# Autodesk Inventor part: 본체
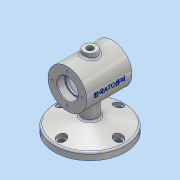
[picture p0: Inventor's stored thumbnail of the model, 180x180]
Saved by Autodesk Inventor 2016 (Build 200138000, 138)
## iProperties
Created: 2018-12
Part Number: 본체
Material: 알루미늄 6061
Document SubType Name: Modeling
Designer: 3sil_cad0123
Density: 2.7 g/cm^3
Appearance: 알루미늄 - 평지
Mass: 685.127 g
Surface Area: 555.63 cm^2
Volume: 253.751 cm^3
Author: 3sil_cad0123
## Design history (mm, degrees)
sketch "스케치1"
  geometry: C1 r 30 at (0, 0); 1 further point
  constraints: 1 centre point, 1 coincident
  dimensions: "d0" = 60 diameter of C1
extrude "돌출1" new body sketch "스케치1" distance "d1" = 70; taper "d2" = 0 deg
node "작업 평면1"
sketch "스케치2"
  geometry: C1 r 25 at (0, 0); 1 further point
  constraints: 1 centre point, 1 coincident
  dimensions: "d3" = 50 diameter of C1
extrude "돌출2" cut sketch "스케치2" stored distance "d4" = 40; taper "d5" = 0 deg
hole "구멍1" diameter "d8" = 28; stored, may be unused: countersink angle "d12" = 90 deg, drill point angle "d14" = 118 deg; dims "d6" = 10, "d7" = 10, "d9" = 6, "d10" = 32, "d11" = 12, "d13" = 8
node "작업 평면2"
sketch "스케치3"
  geometry: C1 r 55 at (0, 35); 1 further point
  constraints: 1 centre point, 1 vertical alignment
  dimensions: "d16" = 110 diameter of C1; "d17" = 35 distance of point (0, 0) C1.centre
extrude "돌출3" join sketch "스케치3" distance "d18" = 11; taper "d19" = 0 deg
sketch "스케치4"
  geometry: C1 r 55 at (0, 0) reference; C2 r 12 at (0, 0); 1 further point
  constraints: 1 centre point, 1 coincident
  dimensions: "d20" = 24 diameter of C2
extrude "돌출4" join sketch "스케치4" stored distance "d21" = 101; taper "d22" = 0 deg
sketch "스케치5"
  geometry: L1 (55, -64)-(55, -75) reference; L2 (55, -75)-(-55, -75) reference; L3 (-55, -75)-(-55, -64) reference; L4 (-55, -64)-(-12, -64) reference; L5 (-12, -64)-(-12, -27.495) reference; L6 (12, -27.495)-(12, -64) reference; L7 (12, -64)-(55, -64) reference; L8 (55, -64)-(-55, -64) reference; L9 (-55, -64)-(4.261, -64); L10 (-55, -64)-(0, -49.263); L11 (-12, -64)-(12, -64) reference; L12 (0, -64)-(0, 0); L13 (-55, -64)-(0, -64); L14 (0, -64)-(55, -64); L15 (0, -49.263)-(55, -64); C1 r 25 at (0, 0) reference; A1 r 30 centre (0, 0) between (12, -27.495) and (-12, -27.495) reference; 1 further point
  constraints: 12 end point, 2 horizontal, 2 point on line, 1 midpoint, 1 vertical
  dimensions: "d96" = 11 distance between parallel lines of L2 L7 (derived); "d97" = 75 deg angle of L1 L15
revolve "회전1" sketch "스케치5" stored, may be unused: angle "d26" = 90 deg
fillet "모깎기1" dims "d27" = 3
node "작업 평면3"
sketch "스케치7"
  geometry: L1 (-30, -35)-(30, -35) reference; C1 r 10 at (0, 0); 1 further point
  constraints: 1 centre point, 1 vertical alignment
  dimensions: "d32" = 20 diameter of C1; "d33" = 35 distance from line of L1 C1.centre
extrude "돌출6" join sketch "스케치7" stored distance "d34" = 40; taper "d35" = 0 deg
fillet "모깎기2" dims "d36" = 3
fillet "모깎기3" dims "d37" = 3
chamfer "모따기1" distance "d38" = 1; stored, may be unused: second distance "d39" = 2, angle "d40" = 45 deg
hole "구멍2" diameter "d43" = 10; stored, may be unused: countersink angle "d47" = 90 deg, drill point angle "d49" = 118 deg; dims "d41" = 10, "d42" = 10, "d44" = 6, "d45" = 32, "d46" = 12, "d48" = 30
fillet "모깎기4" dims "d50" = 3
sketch "스케치8"
  geometry: C1 r 55 at (0, 0) reference; 2 further points
  constraints: 1 horizontal alignment
  dimensions: "d51" = 44 distance of C1.centre point (-44, 0)
hole "구멍3" sketch "스케치8" at (-44, 0) diameter "d52" = 9; stored, may be unused: countersink angle "d56" = 90 deg, drill point angle "d58" = 0 deg; dims "d53" = 6, "d54" = 9, "d55" = 10, "d57" = 10
hole "구멍4" diameter "d61" = 14; stored, may be unused: countersink angle "d65" = 90 deg, drill point angle "d67" = 0 deg; dims "d59" = 10, "d60" = 10, "d62" = 6, "d63" = 9, "d64" = 10, "d66" = 10
sketch "스케치9"
  geometry: C1 r 30 at (0, 0) reference; 1 further point
  constraints: 1 vertical alignment
  dimensions: "d71" = 23 distance of C1.centre point (0, 23)
hole "구멍5" sketch "스케치9" at (0, 23) diameter "d72" = 3.242; stored, may be unused: countersink angle "d76" = 90 deg, drill point angle "d78" = 118 deg; dims "d73" = 8, "d74" = 9, "d75" = 10, "d77" = 10
node "작업 평면6"
sketch "스케치13"
  geometry: L1 (45, 37)-(25, 37) reference; L2 (0, 30)-(70, 30) reference; 2 further points
  constraints: 1 other
  dimensions: "d90" = 35 distance of point (35, 0) point (0, 0); "d92" = 30 distance from line of point (35, 0) L2
feature "엠보싱1" sketch "스케치13" dims "d17" = 35, "d93" = 0.5, "d94" = 0
sketch "스케치14"
  geometry: L1 (-16, -65)-(-13.5, -65) reference; L2 (-13.5, -65)-(-13.5, -75) reference; L3 (-13.5, -75)-(-20, -75) reference; L4 (-20, -75)-(-20, -66.302) reference; L5 (-17.776, -63.404)-(-16, -62.928) reference; L6 (-16, -62.928)-(-16, -65) reference; L7 (83.5, -65)-(86, -65) reference; L8 (86, -65)-(86, -62.928) reference; L9 (86, -62.928)-(87.776, -63.404) reference; L10 (90, -66.302)-(90, -75) reference; L11 (90, -75)-(83.5, -75) reference; L12 (83.5, -75)-(83.5, -65) reference; L13 (70, 17)-(69, 16) reference; L14 (69, 16)-(58, 16) reference; L15 (58, 16)-(58, 14) reference; L16 (58, 14)-(55, 14) reference; L17 (55, 14)-(55, 22) reference; L18 (52, 25)-(40, 25) reference; L19 (40, 25)-(40, 37) reference; L20 (40, 37)-(45, 37) reference; L21 (45, 37)-(45, 33) reference; L22 (48, 30)-(70, 30) reference; L23 (70, 30)-(70, 24.621) reference; L24 (70, 24.621)-(60, 24.621) reference; L25 (60, 24.621)-(59.026, 23) reference; L26 (59.026, 23)-(60, 21.379) reference; L27 (60, 21.379)-(70, 21.379) reference; L28 (70, 21.379)-(70, 17) reference; L29 (15, 22)-(15, 14) reference; L30 (15, 14)-(12, 14) reference; L31 (12, 14)-(12, 16) reference; L32 (12, 16)-(1, 16) reference; L33 (1, 16)-(0, 17) reference; L34 (0, 17)-(0, 21.379) reference; L35 (0, 21.379)-(10, 21.379) reference; L36 (10, 21.379)-(10.974, 23) reference; L37 (10.974, 23)-(10, 24.621) reference; L38 (10, 24.621)-(0, 24.621) reference; L39 (0, 24.621)-(0, 30) reference; L40 (0, 30)-(22, 30) reference; L41 (25, 33)-(25, 37) reference; L42 (25, 37)-(30, 37) reference; L43 (30, 37)-(30, 25) reference; L44 (30, 25)-(18, 25) reference; L45 (18, -25)-(52, -25) reference; L46 (55, -22)-(55, -14) reference; L47 (55, -14)-(58, -14) reference; L48 (58, -14)-(58, -16) reference; L49 (58, -16)-(69, -16) reference; L50 (69, -16)-(70, -17) reference; L51 (70, -17)-(70, -21.379) reference; L52 (70, -21.379)-(60, -21.379) reference; L53 (60, -21.379)-(59.026, -23) reference; L54 (59.026, -23)-(60, -24.621) reference; L55 (60, -24.621)-(70, -24.621) reference; L56 (70, -24.621)-(70, -30) reference; L57 (70, -30)-(50, -30) reference; L58 (47, -33)-(47, -50.176) reference; L59 (49.224, -53.074)-(72, -59.177) reference; L60 (72, -59.177)-(72, -65) reference; L61 (72, -65)-(74.5, -65) reference; L62 (74.5, -65)-(74.5, -75) reference; L63 (74.5, -75)-(-4.5, -75) reference; L64 (-4.5, -75)-(-4.5, -65) reference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; A1 r 3 centre (-17, -66.302) between (-17.776, -63.404) and (-20, -66.302) reference; A2 r 3 centre (87, -66.302) between (90, -66.302) and (87.776, -63.404) reference; A3 r 3 centre (52, 22) between (55, 22) and (52, 25) reference; A4 r 3 centre (18, 22) between (18, 25) and (15, 22) reference; A5 r 3 centre (18, -22) between (15, -22) and (18, -25) reference; A6 r 3 centre (52, -22) between (52, -25) and (55, -22) reference; A7 r 3 centre (50, -50.176) between (47, -50.176) and (49.224, -53.074) reference; A8 r 3 centre (20, -50.176) between (20.776, -53.074) and (23, -50.176) reference; 1 further point
  constraints: 2 end point, 1 vertical, 4 other
  node "절단 모서리 투영2"
fillet "모깎기5" dims "d98" = 0.3
fillet "모깎기6" dims "d99" = 0.3
node "솔리드1"
mirror "대칭1"
pattern_circular "원형 패턴1" dims angle "d69" = 360 deg
pattern_circular "원형 패턴2" dims angle "d80" = 360 deg
mirror "대칭2"
node "절단 모서리 투영1"
other parameters: "d15" = -75, "d31" = -112, "d89" = 30.5
